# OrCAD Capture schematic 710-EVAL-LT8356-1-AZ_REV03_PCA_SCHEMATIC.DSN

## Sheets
1 PAGE1: size Custom; note: HIGH VOLTAGE LED CONTROLLER WITH SSFM
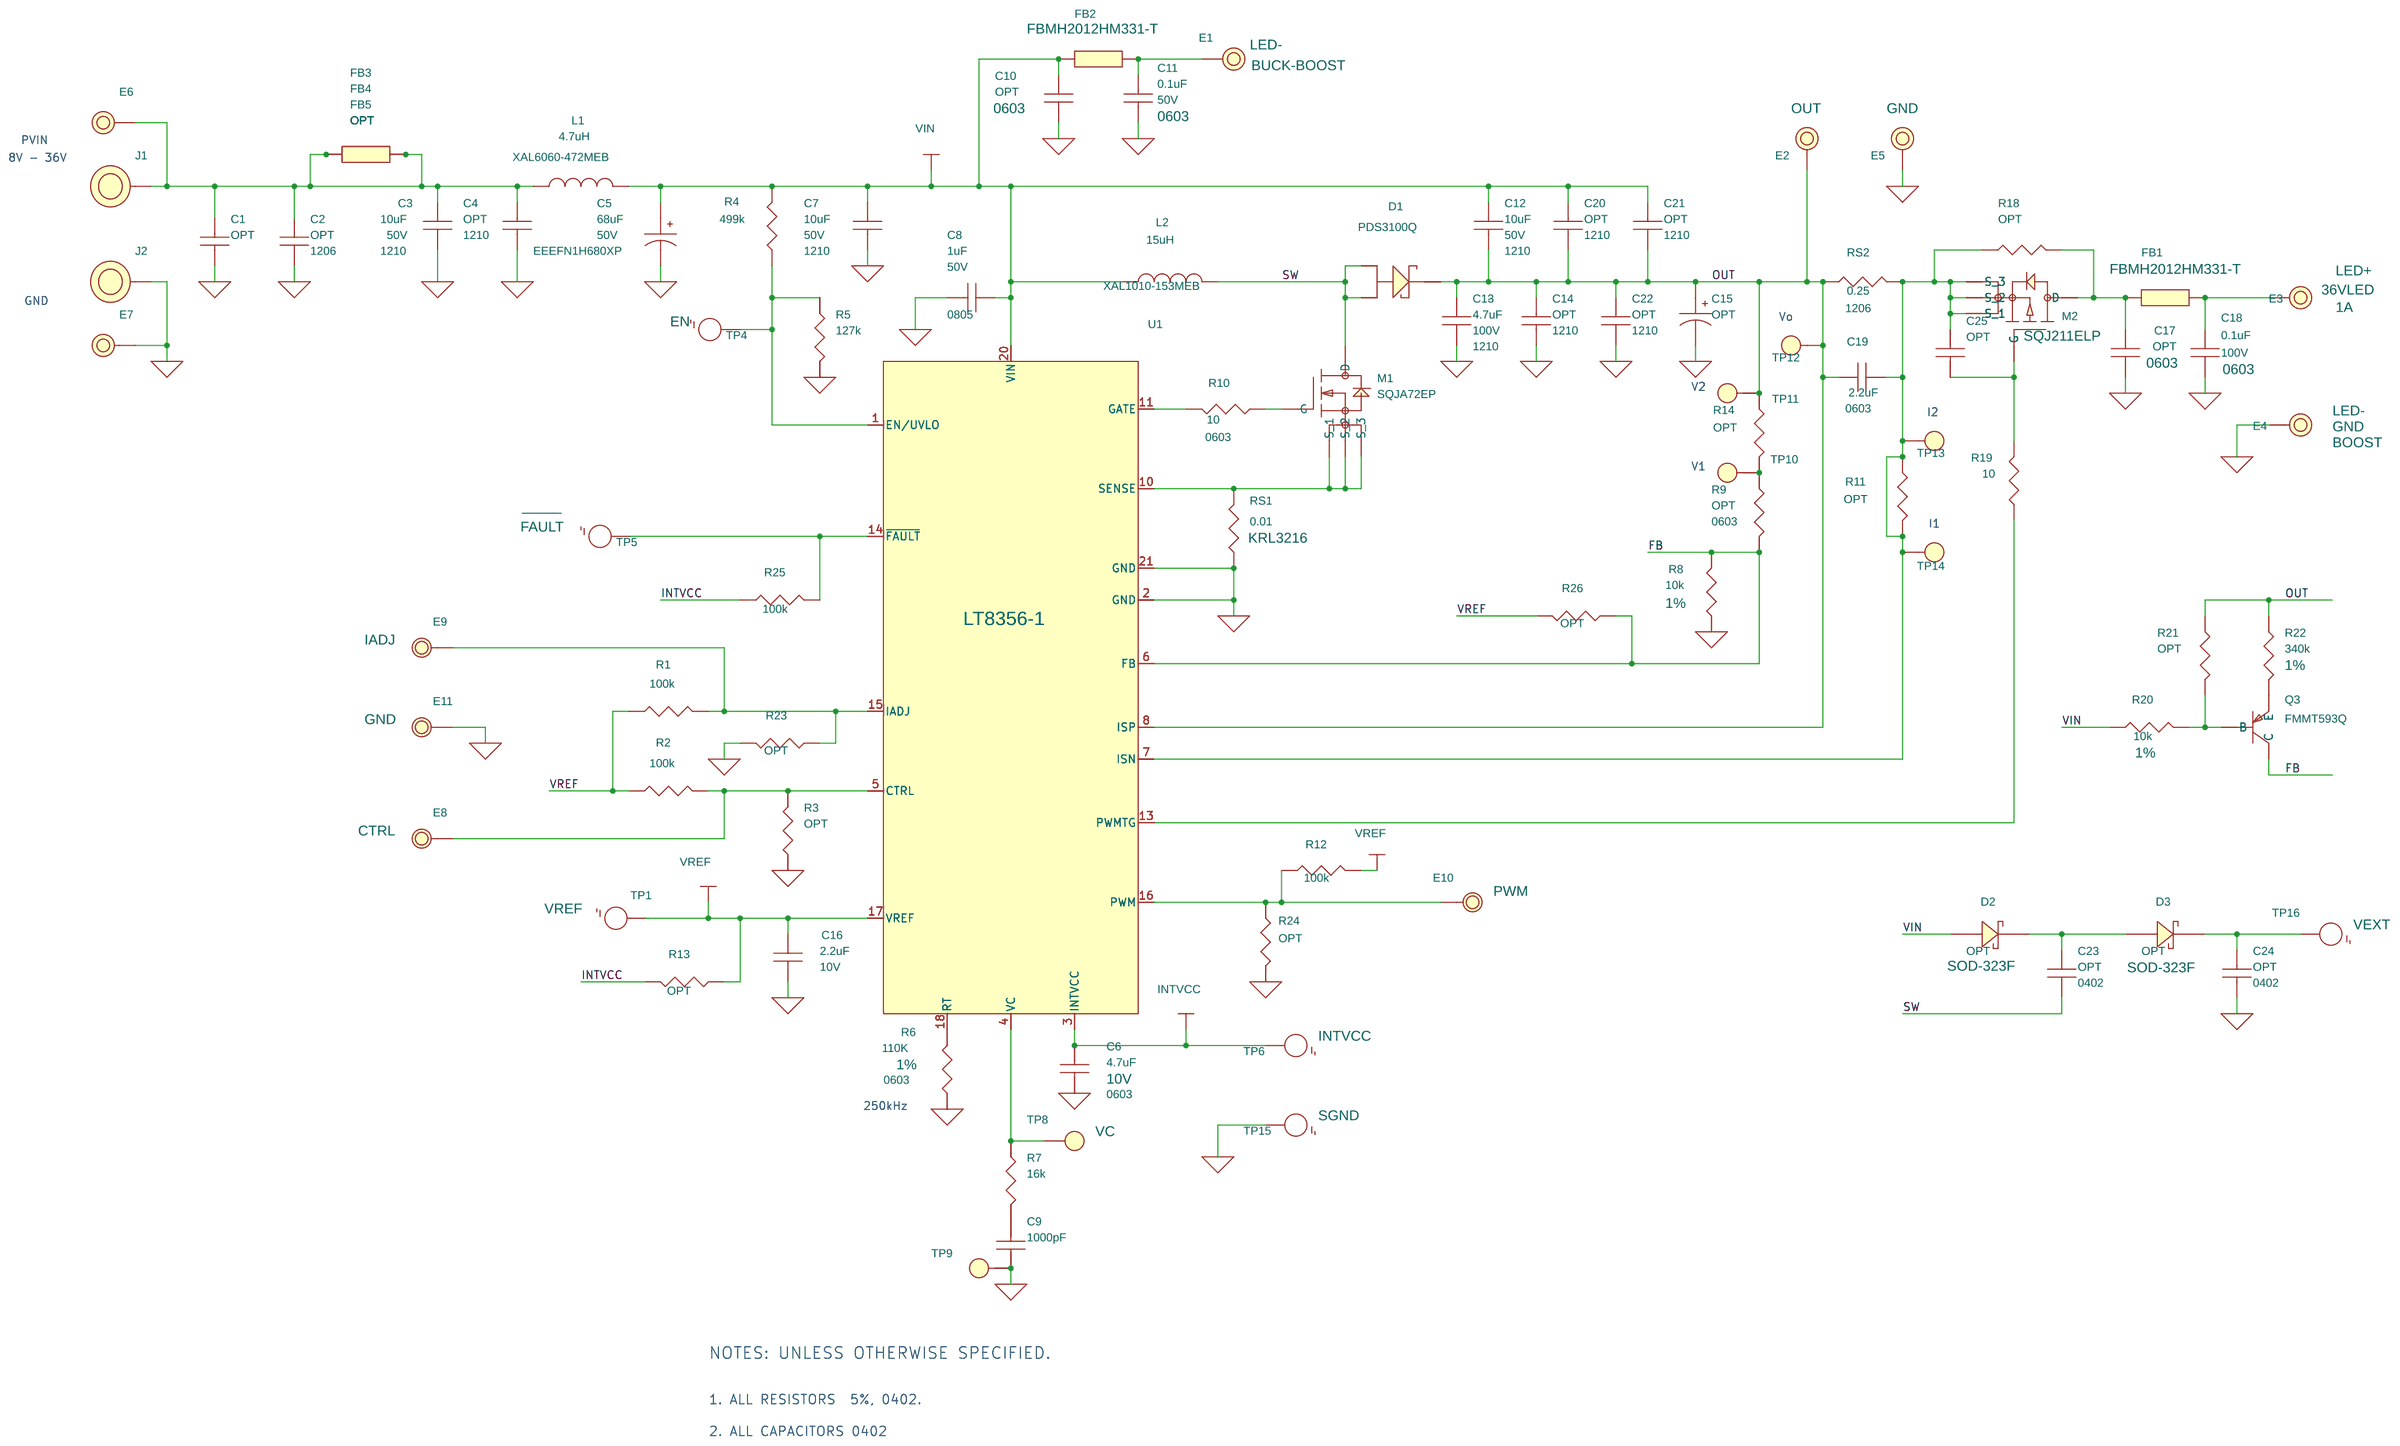
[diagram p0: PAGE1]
2 PAGE2 - HW
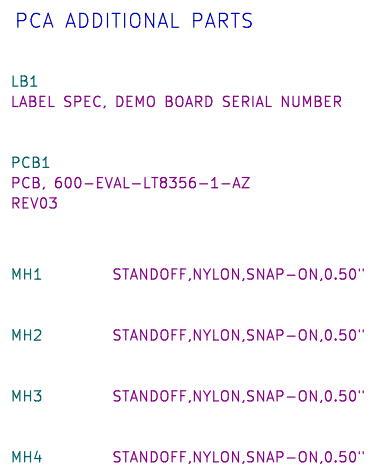
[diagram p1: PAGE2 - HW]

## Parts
sheet PAGE1
C1  OPT  [CC0402N]
C2  OPT  [CC1206N]
C3  10uF  [CC1210N]
C4  OPT  [CC1210N]
C5  68uF  [PANASONIC_FN_6.3X7.7]
C6  4.7uF  [CC0603N]
C7  10uF  [CC1210N]
C8  1uF  [CC0805N]
C9  1000pF  [CC0402N]
C10  OPT  [CC0603N]
C11  0.1uF  [CC0603N]
C12  10uF  [CC1210N]
C13  4.7uF  [CC1210N]
C14  OPT  [CC1210N]
C15  OPT  [CAP_OPT_8]
C16  2.2uF  [CC0402N]
C17  OPT  [CC0603N]
C18  0.1uF  [CC0603N]
C19  2.2uF  [CC0603N]
C20  OPT  [CC1210N]
C21  OPT  [CC1210N]
C22  OPT  [CC1210N]
C23  OPT  [CC0402N]
C24  OPT  [CC0402N]
C25  OPT  [CC0402N]
D1  PDS3100Q  [POWERDI-5]
D2  OPT  [SOD-323F-N]
D3  OPT  [SOD-323F-N]
E1  TEST POINT  [MILLMAX2501]
E2  TEST POINT  [MILLMAX2501]
E3  TEST POINT  [MILLMAX2501]
E4  TEST POINT  [MILLMAX2501]
E5  TEST POINT  [MILLMAX2501]
E6  TEST POINT  [MILLMAX2501]
E7  TEST POINT  [MILLMAX2501]
E8  TEST POINT  [MILLMAX2308]
E9  TEST POINT  [MILLMAX2308]
E10  TEST POINT  [MILLMAX2308]
E11  TEST POINT  [MILLMAX2308]
FB1  330 OHMS@100MHz  [IND0805N]
FB2  330 OHMS@100MHz  [IND0805N]
FB3  OPT  [IND1210N]
FB4  OPT  [IND1210N]
FB5  OPT  [IND1210N]
J1  BANANA JACK  [KEY-575-4]
J2  BANANA JACK  [KEY-575-4]
L1  4.7uH  [COILCRAFT-XAL6060]
L2  15uH  [COILCRAFT-XAL1010]
M1  SQJA72EP  [VISHAY_PPAK-SO-8L]
M2  SQJ211ELP  [VISHAY_PPAK-SO-8L]
Q3  FMMT593Q  [SOT23-3N]
R1  100k  [CR0402N]
R2  100k  [CR0402N]
R3  OPT  [CR0402N]
R4  499k  [CR0402N]
R5  127k  [CR0402N]
R6  110K  [CR0603N]
R7  16k  [CR0402N]
R8  10k  [CR0402N]
R9  OPT  [CR0603N]
R10  10  [CR0603N]
R11  OPT  [CR0402N]
R12  100k  [CR0402N]
R13  OPT  [CR0402N]
R14  OPT  [CR0402N]
R18  OPT  [CR0402N]
R19  10  [CR0402N]
R20  10k  [CR0402N]
R21  OPT  [CR0402N]
R22  340k  [CR0402N]
R23  OPT  [CR0402N]
R24  OPT  [CR0402N]
R25  100k  [CR0402N]
R26  OPT  [CR0402N]
RS1  0.01  [SUSUMU-KRL3216]
RS2  0.25  [CR1206N]
TP1  TEST PAD  [PADSTYLE1]
TP4  TEST PAD  [PADSTYLE1]
TP5  TEST PAD  [PADSTYLE1]
TP6  TEST PAD  [PADSTYLE1]
TP8  TEST PAD  [PADSTYLE1]
TP9  TEST PAD  [PADSTYLE1]
TP10  TEST PAD  [PADSTYLE1]
TP11  TEST PAD  [PADSTYLE1]
TP12  TEST PAD  [PADSTYLE1]
TP13  TEST PAD  [PADSTYLE1]
TP14  TEST PAD  [PADSTYLE1]
TP15  TEST PAD  [PADSTYLE1]
TP16  TEST PAD  [PADSTYLE1]
U1  LT8356JUDCM-1  [LTC-UDCM-20-1793]
sheet PAGE2 - HW
LB1  LABEL  [895-0154_REV01]
MH1  STANDOFF  [KEYSTONE_8829-8834]
MH2  STANDOFF  [KEYSTONE_8829-8834]
MH3  STANDOFF  [KEYSTONE_8829-8834]
MH4  STANDOFF  [KEYSTONE_8829-8834]
PCB1  PCB, 600-EVAL-LT8356-1-AZ

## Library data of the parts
C1 C23-C25 = CAP: CAP., OPTION, 0402; CLASS: DISCRETE; FPLIST: CC0402N,CC0402L,CC0402M; PART_NUMBER: 150-3148; Package Size: 0402; Package Type: SMD
C2 = CAP: CAP., OPTION, 1206; CLASS: DISCRETE; FPLIST: CC1206N,CC1206L,CC1206M; PART_NUMBER: 150-3160; Package Size: 1206; Package Type: SMD
C3 C7 = CAP: CAP.,10uF,X7S,50V,10%,1210,AEC-Q200, NO SUBS ALLOWED; CLASS: DISCRETE; Dielectric Type: X7S; FPLIST: CC1210N,CC1210L,CC1210M; Inventory Qty: 10520; Manufacturer: MURATA; Manufacturer PN: GCM32EC71H106KA03L; PART_NUMBER: 150-2354; Package Size: 1210; Rated Voltage: 50V; Tolerance: 10%
C4 C14 C20-C22 = CAP: CAP., OPTION, 1210; CLASS: DISCRETE; FPLIST: CC1210N,CC1210L,CC1210M; PART_NUMBER: 150-3035; Package Size: 1210; Package Type: SMD
C5 = CAP_P_ALT: CAP.,68uF,ALUM ELECT,50V,20%,6.3x7.7mm,SMD,RADIAL,AEC-Q200; CLASS: DISCRETE; Dielectric Type: ALUM ELECT; FPLIST: PANASONIC_FN_6.3X7.7,PANASONIC_FN_6-3X7-7; Inventory Qty: 0; Manufacturer: PANASONIC; Manufacturer PN: EEEFN1H680XP; PART_NUMBER: 150-1890; Package Size: 6.3x7.7mm,SMD,RADIAL; Package Type: Surface Mount; Rated Voltage: 50V; Tolerance: 20%
C6 = CAP: CAP.,4.7uF,X5R,10V,10%,0603,AEC-Q200; CLASS: DISCRETE; Dielectric Type: X5R; FPLIST: CC0603N,CC0603L,CC0603M; Inventory Qty: 4000; Manufacturer: Taiyo Yuden; Manufacturer PN: LMK107BJ475KAHT; PART_NUMBER: 150-1819; Package Size: 0603; Rated Voltage: 10V; Temperature Coefficient: X5R; Tolerance: 10%
C8 = CAP: CAP.,1uF,X7R,50V,10%,0805,AEC-Q200; CLASS: DISCRETE; Dielectric Type: X7R; FPLIST: CC0805N,CC0805L,CC0805M; Inventory Qty: 8666; Manufacturer: MURATA; Manufacturer PN: GCM21BR71H105KA03L; PART_NUMBER: 150-1750; Package Size: 0805; Rated Voltage: 50V; Temperature Coefficient: X7R; Tolerance: 10%
C9 = CAP: CAP.,1000pF,X7R,50V,10%,0402,AEC-Q200; CLASS: DISCRETE; Dielectric Type: X7R; FPLIST: CC0402N,CC0402L,CC0402M; Inventory Qty: 12960; Manufacturer: MURATA; Manufacturer PN: GCM155R71H102KA37D; PART_NUMBER: 150-1752; Package Size: 0402; Package Type: SMD; Rated Voltage: 50V; Tolerance: 10%
C10 C17 = CAP: CAP., OPTION, 0603; CLASS: DISCRETE; FPLIST: CC0603N,CC0603L,CC0603M; PART_NUMBER: 150-3038; Package Size: 0603; Package Type: SMD
C11 = CAP: CAP.,0.1uF,X7R,50V,10%,0603,AEC-Q200; CLASS: DISCRETE; Dielectric Type: X7R; FPLIST: CC0603N,CC0603L,CC0603M; Inventory Qty: 20275; Manufacturer: TDK; Manufacturer PN: CGA3E2X7R1H104K080AA; PART_NUMBER: 150-0514; Package Size: 0603; Rated Voltage: 50V; Tolerance: 10%
C12 = CAP: CAP.,10uF,X7S,50V,10%,1210,AEC-Q200; CLASS: DISCRETE; Dielectric Type: X7S; FPLIST: CC1210N,CC1210L,CC1210M; Inventory Qty: 0; Manufacturer: MURATA; Manufacturer PN: GCM32EC71H106KA03L; PART_NUMBER: 150-2617; Package Size: 1210; Rated Voltage: 50V; Tolerance: 10%
C13 = CAP: CAP.,4.7uF,X7S,100V,10%,1210,AEC-Q200; CLASS: DISCRETE; Dielectric Type: X7S; FPLIST: CC1210N,CC1210L,CC1210M; Inventory Qty: 14180; Manufacturer: MURATA; Manufacturer PN: GCM32DC72A475KE02L; PART_NUMBER: 150-3376; Package Size: 1210; Rated Voltage: 100V; Tolerance: 10%
C15 = CAP_P_ALT: CAP.,OPTION,ALUM. ELECT.,SMD; CLASS: DISCRETE; FPLIST: USER_ASSIGNED,USER_1,USER_2,USER_3,USER_4,USER_5,USER_6,USER_7,CAP_OPT_6.3,CAP_OPT_8,CAP_OPT_10,CAP_OPT_12.5,CAP_OPT_13,CAP_OPT_16,CAP_OPT_18; PART_NUMBER: 150-0497; Package Type: SMD
C16 = CAP: CAP.,2.2uF,X6S,10V,10%,0402,AEC-Q200; CLASS: DISCRETE; Dielectric Type: X6S; FPLIST: CC0402N,CC0402L,CC0402M; Inventory Qty: 0; Manufacturer: MURATA; Manufacturer PN: GRT155C81A225KE13D; PART_NUMBER: 150-1878; Package Size: 0402; Package Type: SMD; Rated Voltage: 10V; Temperature Coefficient: X6S; Tolerance: 10%
C18 = CAP: CAP.,0.1uF,X7S,100V,10%,0603,AEC-Q200; CLASS: DISCRETE; Dielectric Type: X7S; FPLIST: CC0603N,CC0603L,CC0603M; Inventory Qty: 27710; Manufacturer: TDK; Manufacturer PN: CGA3E3X7S2A104K080AB; PART_NUMBER: 150-2322; Package Size: 0603; Rated Voltage: 100V; Tolerance: 10%
C19 = CAP: CAP.,2.2uF,X5R,25V,10%,0603,AEC-Q200; CLASS: DISCRETE; Dielectric Type: X5R; FPLIST: CC0603N,CC0603L,CC0603M; Inventory Qty: 0; Manufacturer: TAIYO YUDEN; Manufacturer PN: TMK107BBJ225KAHT; PART_NUMBER: 150-0955; Package Size: 0603; Rated Voltage: 25V; Tolerance: 10%
D1 = DIODE_SCHOTTKY_POWERDI5: DIODE,SCHOTTKY,100V,3A,POWERDI5,AEC-Q101; CLASS: DISCRETE; Inventory Qty: 0; Manufacturer: DIODES INC.; Manufacturer PN: PDS3100Q-13; Max Forward Current or Rated Power: 3A; PART_NUMBER: 210-0596; Package Type: PowerDI5; Rated Voltage or Zener Voltage: 100V
D2 D3 = DIODE_SCHOTTKY_A_ALT: DIODE,OPTION, SOD-323F; BOM Notes: BAT46WJ; CLASS: DISCRETE; FPLIST: SOD-323F-N,SOD-323F-L,SOD-323F-M; PART_NUMBER: 210-0458; Package Size: SOD-323F; Package Type: SOD323F-2
E1 = TESTPOINT_.219_MILL-MAX_2501: TEST POINT,TURRET,0.094" MTG. HOLE,PCB 0.062" THK; 10th Part Field: BUCK-BOOST; 11th Part Field: 52V OVLO; 12th Part Field: 60V MAX.; 9th Part Field: LED-; CLASS: IO; FPLIST: MILLMAX2501,MILLMAX2501-2; Inventory Qty: 823526; Manufacturer: MILL-MAX; Manufacturer PN: 2501-2-00-80-00-00-07-0; PART_NUMBER: 260-0003
E2 = TESTPOINT_.219_MILL-MAX_2501: TEST POINT,TURRET,0.094" MTG. HOLE,PCB 0.062" THK; 10th Part Field: GND; 11th Part Field: 52V OVLO; 12th Part Field: 60V MAX.; 9th Part Field: OUT; CLASS: IO; FPLIST: MILLMAX2501,MILLMAX2501-2; Inventory Qty: 823526; Manufacturer: MILL-MAX; Manufacturer PN: 2501-2-00-80-00-00-07-0; PART_NUMBER: 260-0003
E3 = TESTPOINT_.219_MILL-MAX_2501: TEST POINT,TURRET,0.094" MTG. HOLE,PCB 0.062" THK; 10th Part Field: 36VLED; 11th Part Field: 1A; 12th Part Field: 60V MAX.; 9th Part Field: LED+; CLASS: IO; FPLIST: MILLMAX2501,MILLMAX2501-2; Inventory Qty: 823526; Manufacturer: MILL-MAX; Manufacturer PN: 2501-2-00-80-00-00-07-0; PART_NUMBER: 260-0003
E4 E5 = TESTPOINT_.219_MILL-MAX_2501: TEST POINT,TURRET,0.094" MTG. HOLE,PCB 0.062" THK; 10th Part Field: GND; 11th Part Field: BOOST; 12th Part Field: 60V MAX.; 9th Part Field: LED-; CLASS: IO; FPLIST: MILLMAX2501,MILLMAX2501-2; Inventory Qty: 823526; Manufacturer: MILL-MAX; Manufacturer PN: 2501-2-00-80-00-00-07-0; PART_NUMBER: 260-0003
E6 = TESTPOINT_.219_MILL-MAX_2501: TEST POINT,TURRET,0.094" MTG. HOLE,PCB 0.062" THK; 10th Part Field: GND; 11th Part Field: 52V OVLO; 12th Part Field: 60V MAX.; 9th Part Field: BAT+; CLASS: IO; FPLIST: MILLMAX2501,MILLMAX2501-2; Inventory Qty: 823526; Manufacturer: MILL-MAX; Manufacturer PN: 2501-2-00-80-00-00-07-0; PART_NUMBER: 260-0003
E7 = TESTPOINT_.219_MILL-MAX_2501: TEST POINT,TURRET,0.094" MTG. HOLE,PCB 0.062" THK; 10th Part Field: GND; 11th Part Field: GND; 12th Part Field: GND; 9th Part Field: GND; CLASS: IO; FPLIST: MILLMAX2501,MILLMAX2501-2; Inventory Qty: 823526; Manufacturer: MILL-MAX; Manufacturer PN: 2501-2-00-80-00-00-07-0; PART_NUMBER: 260-0003
E8 = TEST_POINT_.156_MILL-MAX_2308_A: TEST POINT,TURRET,0.064" MTG. HOLE,PCB 0.062" THK; 9th Part Field: CTRL; CLASS: IO; FPLIST: MILLMAX2308,MILLMAX2308-2; Inventory Qty: 1142083; Manufacturer: MILL-MAX; Manufacturer PN: 2308-2-00-80-00-00-07-0; PART_NUMBER: 260-0004
E9 = TEST_POINT_.156_MILL-MAX_2308_A: TEST POINT,TURRET,0.064" MTG. HOLE,PCB 0.062" THK; 9th Part Field: IADJ; CLASS: IO; FPLIST: MILLMAX2308,MILLMAX2308-2; Inventory Qty: 1142083; Manufacturer: MILL-MAX; Manufacturer PN: 2308-2-00-80-00-00-07-0; PART_NUMBER: 260-0004
E10 = TEST_POINT_.156_MILL-MAX_2308_A: TEST POINT,TURRET,0.064" MTG. HOLE,PCB 0.062" THK; 9th Part Field: PWM; CLASS: IO; FPLIST: MILLMAX2308,MILLMAX2308-2; Inventory Qty: 1142083; Manufacturer: MILL-MAX; Manufacturer PN: 2308-2-00-80-00-00-07-0; PART_NUMBER: 260-0004
E11 = TEST_POINT_.156_MILL-MAX_2308_A: TEST POINT,TURRET,0.064" MTG. HOLE,PCB 0.062" THK; 9th Part Field: GND; CLASS: IO; FPLIST: MILLMAX2308,MILLMAX2308-2; Inventory Qty: 1142083; Manufacturer: MILL-MAX; Manufacturer PN: 2308-2-00-80-00-00-07-0; PART_NUMBER: 260-0004
FB1 FB2 = FERRITEBEAD_ALT1: IND.,330 OHMS@100MHz,FERRITE BEAD,25%,1.8A,80mOHMS,0805,1LN; CLASS: DISCRETE; FPLIST: IND0805N,IND0805L,IND0805M; Inventory Qty: 4000; Manufacturer: TAIYO YUDEN; Manufacturer PN: FBMH2012HM331-T; PART_NUMBER: 200-0778; Package Size: 0805; Tolerance: 25%
FB3-FB5 = FERRITEBEAD_ALT1: IND.,OPTION,FERRITE BEAD,1210; CLASS: DISCRETE; FPLIST: IND1210N,IND1210L,IND1210M; PART_NUMBER: 200-0785; Package Size: 1210
J1 J2 = BANANA_KEYSTONE-575-4: CONN.,BANANA JACK,FEMALE,THT,NON-INSULATED,SWAGE,0.218"; CLASS: IO; Inventory Qty: 203061; Manufacturer: KEYSTONE; Manufacturer PN: 575-4; PART_NUMBER: 250-0428
L1 = IND_ALT: IND.,4.7uH,PWR,SHIELDED,20%,11A,14.4mOHMS,6.76x6.56mm,XAL6060,AEC-Q200; CLASS: DISCRETE; Inventory Qty: 100; Manufacturer: COILCRAFT; Manufacturer PN: XAL6060-472MEB; PART_NUMBER: 200-0758; Package Size: 6.76x6.56mm; Tolerance: 20%
L2 = IND: IND.,15uH,PWR,SHIELDED,20%,13.8A,18.6mOHMS,11.8x10.5mm,XAL1010,AEC-Q200; CLASS: DISCRETE; Inventory Qty: 1104; Manufacturer: COILCRAFT; Manufacturer PN: XAL1010-153MEB; PART_NUMBER: 200-0171; Package Size: 11.8x10.5mm,XAL1010; Tolerance: 20%
M1 = 5P_N-CH_TYPE1D: XSTR.,MOSFET,N-CH,100V,37A,PowerPAK SO-8L,AEC-Q101; CLASS: DISCRETE; Inventory Qty: 0; Manufacturer: VISHAY; Manufacturer PN: SQJA72EP-T1_GE3; PART_NUMBER: 240-0565; Package Type: PowerPAK SO-8L; Rated Voltage: 100V
M2 = 5P_P-CH_TYPE1D: XSTR.,MOSFET,P-CH,100V,33.6A,PowerPAK SO-8L,AEC-Q101; CLASS: DISCRETE; Inventory Qty: 0; Manufacturer: VISHAY; Manufacturer PN: SQJ211ELP-T1_GE3; PART_NUMBER: 240-0610; Package Size: PowerPAK SO-8; Package Type: PowerPAK SO-8L; Polarity: P Channel; Rated Voltage: 100V
Q3 = 3P_PNP_TYPE1A: XSTR.,PNP,100V,1A,SOT-23-3,AEC-Q101; CLASS: DISCRETE; FPLIST: SOT23-3N,SOT23-3L,SOT23-3M; Inventory Qty: 0; Manufacturer: DIODES INC.; Manufacturer PN: FMMT593QTA; PART_NUMBER: 240-0611; Package Type: SOT-23-3; Rated Voltage: 100V
R1 R2 R12 R25 = RES: RES.,100k OHMS,5%,1/16W,0402,AEC-Q200; CLASS: DISCRETE; FPLIST: CR0402N,CR0402L,CR0402M; Inventory Qty: 59032; Manufacturer: NIC; Manufacturer PN: NRC04J104TRF; PART_NUMBER: 100-0359; Package Size: 0402; Rated Power: 1/16W; Temperature Coefficient: 200ppm/C; Tolerance: 5%
R3 R11 R13 R14 R18 R21 R23 R24 R26 = RES: RES., OPTION, 0402; CLASS: DISCRETE; FPLIST: CR0402N,CR0402L,CR0402M; PART_NUMBER: 100-0357; Package Size: 0402
R4 = RES: RES.,499k OHMS,1%,1/16W,0402,AEC-Q200; CLASS: DISCRETE; FPLIST: CR0402N,CR0402L,CR0402M; Inventory Qty: 39488; Manufacturer: NIC; Manufacturer PN: NRC04F4993TRF; PART_NUMBER: 100-2665; Package Size: 0402; Rated Power: 1/16W; Temperature Coefficient: 100ppm; Tolerance: 1%
R5 = RES: RES.,127k OHMS,1%,1/16W,0402,AEC-Q200; CLASS: DISCRETE; FPLIST: CR0402N,CR0402L,CR0402M; Inventory Qty: 0; Manufacturer: VISHAY; Manufacturer PN: CRCW0402127KFKED; PART_NUMBER: 100-2516; Package Size: 0402; Rated Power: 1/16W; Temperature Coefficient: 100ppm/C; Tolerance: 1%
R6 = RES: RES.,110k OHMS,1%,1/10W,0603,AEC-Q200; 1st_Part_Field: 1%; CLASS: DISCRETE; FPLIST: CR0603N,CR0603L,CR0603M; Inventory Qty: 70777; Manufacturer: PANASONIC; Manufacturer PN: ERJ3EKF1103V; PART_NUMBER: 100-0789; Package Size: 0603; Rated Power: 1/10W; Temperature Coefficient: +/-100PPM; Tolerance: 1%
R7 = RES: RES.,16K OHMS,5%,1/16W,0402,AEC-Q200; CLASS: DISCRETE; FPLIST: CR0402N,CR0402L,CR0402M; Inventory Qty: 0; Manufacturer: VISHAY; Manufacturer PN: CRCW040216K0JNED; PART_NUMBER: 100-1875; Package Size: 0402; Rated Power: 1/16W; Temperature Coefficient: +/-200PPM; Tolerance: 5%
R8 R20 = RES: RES.,10k OHMS,1%,1/16W,0402,AEC-Q200; CLASS: DISCRETE; FPLIST: CR0402N,CR0402L,CR0402M; Inventory Qty: 76366; Manufacturer: VISHAY; Manufacturer PN: CRCW040210K0FKED; PART_NUMBER: 100-2545; Package Size: 0402; Rated Power: 1/16W; Temperature Coefficient: 100ppm/C; Tolerance: 1%
R9 = RES: RES., OPTION, 0603; CLASS: DISCRETE; FPLIST: CR0603N,CR0603L,CR0603M; PART_NUMBER: 100-2374; Package Size: 0603
R10 = RES: RES.,10 OHMS,5%,1/10W,0603,AEC-Q200; CLASS: DISCRETE; FPLIST: CR0603N,CR0603L,CR0603M; Inventory Qty: 57688; Manufacturer: PANASONIC; Manufacturer PN: ERJ3GEYJ100V; PART_NUMBER: 100-2058; Package Size: 0603; Rated Power: 1/10W; Temperature Coefficient: 200ppm/C; Tolerance: 5%
R19 = RES: RES.,10 OHMS,5%,1/16W,0402,AEC-Q200; CLASS: DISCRETE; FPLIST: CR0402N,CR0402L,CR0402M; Inventory Qty: 18730; Manufacturer: VISHAY; Manufacturer PN: CRCW040210R0JNED; PART_NUMBER: 100-1227; Package Size: 0402; Rated Power: 1/16W; Temperature Coefficient: +/-200ppm; Tolerance: 5%
R22 = RES: RES.,340k OHMS,1%,1/16W,0402,AEC-Q200; CLASS: DISCRETE; FPLIST: CR0402N,CR0402L,CR0402M; Inventory Qty: 19024; Manufacturer: YAGEO; Manufacturer PN: AC0402FR-07340KL; PART_NUMBER: 100-0950; Package Size: 0402; Rated Power: 1/16W; Temperature Coefficient: 100ppm; Tolerance: 1%
RS1 = RES: RES.,0.01 OHM,1%,1.5A,1206, LONG-SIDE TERM.,METAL, SENSE, AEC-Q200; 9th Part Field: KRL3216; CLASS: DISCRETE; Inventory Qty: 0; Manufacturer: SUSUMU; Manufacturer PN: KRL3216E-C-R010-F-T1; PART_NUMBER: 100-1179; Package Size: 1206, LONG-SIDE TERM.; Rated Power: 1.5A; Temperature Coefficient: +/-50ppm; Tolerance: 1%
RS2 = RES: RES.,0.25 OHM,1%,1/2W,1206,SENSE,AEC-Q200; CLASS: DISCRETE; FPLIST: CR1206N,CR1206L,CR1206M; Inventory Qty: 0; Manufacturer: YAGEO; Manufacturer PN: PT1206FR-7W0R25L; PART_NUMBER: 100-1878; Package Size: 1206; Rated Power: 1/2W; Temperature Coefficient: +/-75ppm; Tolerance: 1%
TP1 = TESTPOINT_FILLED_CIRCLE: TESTPOINT, PCB COPPER FEATURE; 10th Part Field: _____; 9th Part Field: VREF; CLASS: IO; FPLIST: PADSTYLE1,PADSTYLE2,PADSTYLE3,PADSTYLE4,PADSTYLE5,PADSTYLE6,PADSTYLE7,PADSTYLE8; Manufacturer: N/A; Manufacturer PN: N/A
TP4 = TESTPOINT_FILLED_CIRCLE: TESTPOINT, PCB COPPER FEATURE; 9th Part Field: EN; CLASS: IO; FPLIST: PADSTYLE1,PADSTYLE2,PADSTYLE3,PADSTYLE4,PADSTYLE5,PADSTYLE6,PADSTYLE7,PADSTYLE8; Manufacturer: N/A; Manufacturer PN: N/A
TP5 = TESTPOINT_FILLED_CIRCLE: TESTPOINT, PCB COPPER FEATURE; 10th Part Field: _____; 9th Part Field: FAULT; CLASS: IO; FPLIST: PADSTYLE1,PADSTYLE2,PADSTYLE3,PADSTYLE4,PADSTYLE5,PADSTYLE6,PADSTYLE7,PADSTYLE8; Manufacturer: N/A; Manufacturer PN: N/A
TP6 = TESTPOINT_FILLED_CIRCLE: TESTPOINT, PCB COPPER FEATURE; 10th Part Field: _____; 9th Part Field: INTVCC; CLASS: IO; FPLIST: PADSTYLE1,PADSTYLE2,PADSTYLE3,PADSTYLE4,PADSTYLE5,PADSTYLE6,PADSTYLE7,PADSTYLE8; Manufacturer: N/A; Manufacturer PN: N/A
TP8-TP14 = PAD_STYLE_C: TESTPOINT, PCB COPPER FEATURE; 9th Part Field: VC; CLASS: IO; FPLIST: PADSTYLE1,PADSTYLE2,PADSTYLE3,PADSTYLE4,PADSTYLE5,PADSTYLE6,PADSTYLE7,PADSTYLE8; Manufacturer: N/A; Manufacturer PN: N/A
TP15 = TESTPOINT_FILLED_CIRCLE: TESTPOINT, PCB COPPER FEATURE; 10th Part Field: _____; 9th Part Field: SGND; CLASS: IO; FPLIST: PADSTYLE1,PADSTYLE2,PADSTYLE3,PADSTYLE4,PADSTYLE5,PADSTYLE6,PADSTYLE7,PADSTYLE8; Manufacturer: N/A; Manufacturer PN: N/A
TP16 = TESTPOINT_FILLED_CIRCLE: TESTPOINT, PCB COPPER FEATURE; 10th Part Field: _____; 9th Part Field: VEXT; CLASS: IO; FPLIST: PADSTYLE1,PADSTYLE2,PADSTYLE3,PADSTYLE4,PADSTYLE5,PADSTYLE6,PADSTYLE7,PADSTYLE8; Manufacturer: N/A; Manufacturer PN: N/A
U1 = LT8356-UDCM-1: IC,LED DRIVER CTRLR,QFN-20; 9th Part Field: LT8356-1; CLASS: IC; Inventory Qty: 0; Manufacturer: ANALOG DEVICES; Manufacturer PN: LT8356JUDCM-1#PBF; PART_NUMBER: LT8356JUDCM-1#PBF; Package Type: QFN-20
LB1 = BLANK_LABEL: LABEL SPEC, DEMO BOARD SERIAL NUMBER; Inventory Qty: 0; Manufacturer: BRADY; Manufacturer PN: THT-96-717-10; PART_NUMBER: 895-0154
MH1-MH4 = BLANK_MECHANICAL_PART: STANDOFF,NYLON,SNAP-ON,0.50"; CLASS: DISCRETE; FPLIST: KEYSTONE_8829-8834,KEYSTONE_8833,MTG-8831; Inventory Qty: 214842; Manufacturer: KEYSTONE; Manufacturer PN: 8833; PART_NUMBER: 763-0007
PCB1 = BLANK_PCB_PART: BOM Notes: REV03; CLASS: DISCRETE; Inventory Qty: 0; Manufacturer: ADI APPROVED SUPPLIER; Manufacturer PN: 600-EVAL-LT8356-1-AZ; PART_NUMBER: 600-EVAL-LT8356-1-AZ

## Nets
GND_SIGNAL: C1.2 C2.2 C3.2 C4.2 C5.2 C6.2 C7.2 C8.2 C9.1 C10.2 C11.2 C13.2 C14.2 C15.2 C16.2 C17.2 C18.2 C22.2 C24.2 E4.1 E5.1 E7.1 E11.1 J2.1 R3.2 R5.2 R6.2 R8.1 R23.1 R24.2 RS1.1 TP9.1 TP15.1 U1.2(GND) U1.21(GND)
VIN: C5.1 C7.1 C8.1 C10.1 C12.1 C20.1 C21.1 D2.2(A) FB2.2 L1.1 L2.2 R4.1 R20.1 U1.20(VIN)
FB: Q3.3(C) R8.2 R9.1 R26.2 U1.6(FB)
INTVCC: C6.1 R13.1 R25.1 TP6.1 U1.3(INTVCC)
OUT: C12.2 C13.1 C14.1 C15.1 C19.1 C20.2 C21.2 C22.1 D1.1 E2.1 R14.2 R21.1 R22.1 RS2.1 TP11.1 TP12.1 U1.8(ISP)
SW: C23.2 D1.2 D1.3 L2.1 M1.5(D)
VREF: C16.1 R1.1 R2.1 R12.2 R13.2 R26.1 TP1.1 U1.17(VREF)
N16886028: C1.1 C2.1 C3.1 C4.1 E6.1 FB3.1 FB3.2 FB4.1 FB4.2 FB5.1 FB5.2 J1.1 L1.2
N16886185: R4.2 R5.1 TP4.1 U1.1(EN/UVLO)
N16887921: E10.1 R12.1 R24.1 U1.16(PWM)
N16888275: R10.1 U1.11(GATE)
N16888310: M1.1(S) M1.2(S) M1.3(S) RS1.2 U1.10(SENSE)
N16890113: C19.2 C25.1 M2.1(S) M2.2(S) M2.3(S) R11.1 R11.2 R18.1 RS2.2 TP13.1 TP14.1 U1.7(ISN)
N16891139: R19.2 U1.13(PWMTG)
N16898515: C11.1 E1.1 FB2.1
N16905152: C17.1 FB1.2 M2.5(D) R18.2
N16906560: C18.1 E3.1 FB1.1
N16907513: C25.2 M2.4(G) R19.1
N16913921: R7.1 TP8.1 U1.4(VC)
N16916665: R25.2 TP5.1 U1.14(~{FAULT})
N16916691: E9.1 R1.2 R23.2 U1.15(IADJ)
N16916705: E8.1 R2.2 R3.1 U1.5(CTRL)
N16924534: Q3.1(B) R20.2 R21.2
N16941601: M1.4(G) R10.2
N16957945: C23.1 D2.1(C) D3.2(A)
N16958055: C24.1 D3.1(C) TP16.1
N16974920: R9.2 R14.1 TP10.1
N16974922: Q3.2(E) R22.2
N16974923: C9.2 R7.2
N16979482: R6.1 U1.18(RT)

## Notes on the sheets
sheet 1
- PVIN
- 8V - 36V
- GND
- Vo
- V2
- I2
- V1
- I1
- 250kHz
- NOTES: UNLESS OTHERWISE SPECIFIED.
- 1. ALL RESISTORS  5%, 0402.
- 2. ALL CAPACITORS 0402
sheet 2
- PCA ADDITIONAL PARTS
